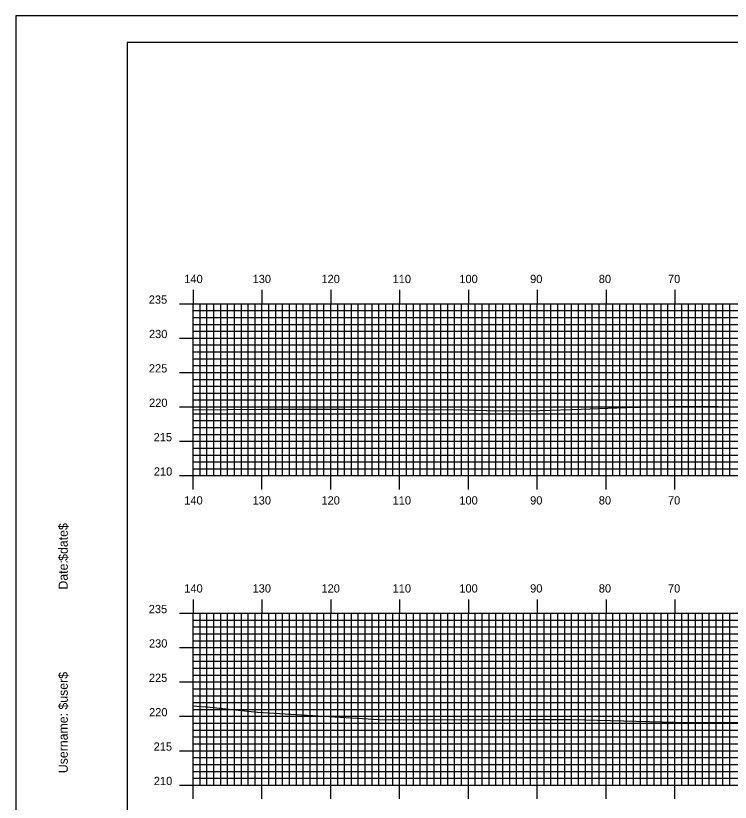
# Model space of a CAD drawing. Extents: x 1804290 to 1804634, y 442591 to 442811.
# Drawn here: x 1804290.4 to 1804394.2, y 442696.2 to 442810.5 of the extents above; entities that cross this region are included whole.
import ezdxf

# ---------------------------------------------------------------- set-up
doc = ezdxf.new("R2010")
doc.units = 0
for name, color, linetype in [('BORDER', 7, 'Continuous'), ('H_V ANNOTATION', 7, 'Continuous'), ('MAJOR', 7, 'Continuous'), ('MINOR', 7, 'Continuous'), ('PLOT BOUNDARY', 7, 'Continuous'), ('S_Roadway_Centerline', 7, 'Continuous')]:
    doc.layers.add(name, color=color, linetype=linetype)

msp = doc.modelspace()

# ---------------------------------------------------------------- linework, layer by layer
at = {"layer": 'BORDER'}
msp.add_lwpolyline([(1804306.57, 442596.67), (1804626.57, 442596.67), (1804626.57, 442806.67), (1804306.57, 442806.67)], close=True, dxfattribs=at)
at = {"layer": 'MAJOR'}
for p, q in [((1804316.17, 442770.67), (1804316.17, 442768.67)), ((1804326.17, 442770.67), (1804326.17, 442768.67)), ((1804336.17, 442770.67), (1804336.17, 442768.67)), ((1804346.17, 442770.67), (1804346.17, 442768.67)), ((1804356.17, 442770.67), (1804356.17, 442768.67)), ((1804366.17, 442770.67), (1804366.17, 442768.67)), ((1804376.17, 442770.67), (1804376.17, 442768.67)), ((1804386.17, 442770.67), (1804386.17, 442768.67)), ((1804314.16, 442768.67), (1804316.17, 442768.67)), ((1804316.17, 442768.67), (1804596.17, 442768.67)), ((1804316.17, 442743.67), (1804316.17, 442768.67)), ((1804316.17, 442743.67), (1804316.17, 442768.67)), ((1804316.17, 442768.67), (1804596.17, 442768.67)), ((1804326.17, 442743.67), (1804326.17, 442768.67)), ((1804336.17, 442743.67), (1804336.17, 442768.67)), ((1804346.17, 442743.67), (1804346.17, 442768.67)), ((1804356.17, 442743.67), (1804356.17, 442768.67)), ((1804366.17, 442743.67), (1804366.17, 442768.67)), ((1804376.17, 442743.67), (1804376.17, 442768.67)), ((1804386.17, 442743.67), (1804386.17, 442768.67)), ((1804314.16, 442763.67), (1804316.17, 442763.67)), ((1804316.17, 442763.67), (1804596.17, 442763.67)), ((1804314.16, 442758.67), (1804316.17, 442758.67)), ((1804316.17, 442758.67), (1804596.17, 442758.67)), ((1804314.16, 442753.67), (1804316.17, 442753.67)), ((1804316.17, 442753.67), (1804596.17, 442753.67)), ((1804314.16, 442748.67), (1804316.17, 442748.67)), ((1804316.17, 442748.67), (1804596.17, 442748.67)), ((1804314.16, 442743.67), (1804316.17, 442743.67)), ((1804316.17, 442743.67), (1804596.17, 442743.67)), ((1804316.17, 442743.67), (1804596.17, 442743.67)), ((1804316.17, 442741.66), (1804316.17, 442743.67)), ((1804326.17, 442741.66), (1804326.17, 442743.67)), ((1804336.17, 442741.66), (1804336.17, 442743.67)), ((1804346.17, 442741.66), (1804346.17, 442743.67)), ((1804356.17, 442741.66), (1804356.17, 442743.67)), ((1804366.17, 442741.66), (1804366.17, 442743.67)), ((1804376.17, 442741.66), (1804376.17, 442743.67)), ((1804386.17, 442741.66), (1804386.17, 442743.67)), ((1804316.17, 442725.67), (1804316.17, 442723.67)), ((1804326.17, 442725.67), (1804326.17, 442723.67)), ((1804336.17, 442725.67), (1804336.17, 442723.67)), ((1804346.17, 442725.67), (1804346.17, 442723.67)), ((1804356.17, 442725.67), (1804356.17, 442723.67)), ((1804366.17, 442725.67), (1804366.17, 442723.67)), ((1804376.17, 442725.67), (1804376.17, 442723.67)), ((1804386.17, 442725.67), (1804386.17, 442723.67)), ((1804314.16, 442723.67), (1804316.17, 442723.67)), ((1804316.17, 442723.67), (1804596.17, 442723.67)), ((1804316.17, 442698.67), (1804316.17, 442723.67)), ((1804316.17, 442698.67), (1804316.17, 442723.67)), ((1804316.17, 442723.67), (1804596.17, 442723.67)), ((1804326.17, 442698.67), (1804326.17, 442723.67)), ((1804336.17, 442698.67), (1804336.17, 442723.67)), ((1804346.17, 442698.67), (1804346.17, 442723.67)), ((1804356.17, 442698.67), (1804356.17, 442723.67)), ((1804366.17, 442698.67), (1804366.17, 442723.67)), ((1804376.17, 442698.67), (1804376.17, 442723.67)), ((1804386.17, 442698.67), (1804386.17, 442723.67)), ((1804314.16, 442718.67), (1804316.17, 442718.67)), ((1804316.17, 442718.67), (1804596.17, 442718.67)), ((1804314.16, 442713.67), (1804316.17, 442713.67)), ((1804316.17, 442713.67), (1804596.17, 442713.67)), ((1804314.16, 442708.67), (1804316.17, 442708.67)), ((1804316.17, 442708.67), (1804596.17, 442708.67)), ((1804314.16, 442703.67), (1804316.17, 442703.67)), ((1804316.17, 442703.67), (1804596.17, 442703.67)), ((1804314.16, 442698.67), (1804316.17, 442698.67)), ((1804316.17, 442698.67), (1804596.17, 442698.67)), ((1804316.17, 442698.67), (1804596.17, 442698.67)), ((1804316.17, 442696.66), (1804316.17, 442698.67)), ((1804326.17, 442696.66), (1804326.17, 442698.67)), ((1804336.17, 442696.66), (1804336.17, 442698.67)), ((1804346.17, 442696.66), (1804346.17, 442698.67)), ((1804356.17, 442696.66), (1804356.17, 442698.67)), ((1804366.17, 442696.66), (1804366.17, 442698.67)), ((1804376.17, 442696.66), (1804376.17, 442698.67)), ((1804386.17, 442696.66), (1804386.17, 442698.67))]:
    msp.add_line(p, q, dxfattribs=at)
at = {"layer": 'MINOR'}
for p, q in [((1804316.17, 442767.67), (1804596.17, 442767.67)), ((1804316.17, 442767.67), (1804318.17, 442767.67)), ((1804317.17, 442743.67), (1804317.17, 442768.67)), ((1804318.17, 442743.67), (1804318.17, 442768.67)), ((1804319.17, 442743.67), (1804319.17, 442768.67)), ((1804320.17, 442743.67), (1804320.17, 442768.67)), ((1804321.17, 442743.67), (1804321.17, 442768.67)), ((1804322.17, 442743.67), (1804322.17, 442768.67)), ((1804323.17, 442743.67), (1804323.17, 442768.67)), ((1804324.17, 442743.67), (1804324.17, 442768.67)), ((1804325.17, 442743.67), (1804325.17, 442768.67)), ((1804327.17, 442743.67), (1804327.17, 442768.67)), ((1804328.17, 442743.67), (1804328.17, 442768.67)), ((1804329.17, 442743.67), (1804329.17, 442768.67)), ((1804330.17, 442743.67), (1804330.17, 442768.67)), ((1804331.17, 442743.67), (1804331.17, 442768.67)), ((1804332.17, 442743.67), (1804332.17, 442768.67)), ((1804333.17, 442743.67), (1804333.17, 442768.67)), ((1804334.17, 442743.67), (1804334.17, 442768.67)), ((1804335.17, 442743.67), (1804335.17, 442768.67)), ((1804337.17, 442743.67), (1804337.17, 442768.67)), ((1804338.17, 442743.67), (1804338.17, 442768.67)), ((1804339.17, 442743.67), (1804339.17, 442768.67)), ((1804340.17, 442743.67), (1804340.17, 442768.67)), ((1804341.17, 442743.67), (1804341.17, 442768.67)), ((1804342.17, 442743.67), (1804342.17, 442768.67)), ((1804343.17, 442743.67), (1804343.17, 442768.67)), ((1804344.17, 442743.67), (1804344.17, 442768.67)), ((1804345.17, 442743.67), (1804345.17, 442768.67)), ((1804347.17, 442743.67), (1804347.17, 442768.67)), ((1804348.17, 442743.67), (1804348.17, 442768.67)), ((1804349.17, 442743.67), (1804349.17, 442768.67)), ((1804350.17, 442743.67), (1804350.17, 442768.67)), ((1804351.17, 442743.67), (1804351.17, 442768.67)), ((1804352.17, 442743.67), (1804352.17, 442768.67)), ((1804353.17, 442743.67), (1804353.17, 442768.67)), ((1804354.17, 442743.67), (1804354.17, 442768.67)), ((1804355.17, 442743.67), (1804355.17, 442768.67)), ((1804357.17, 442743.67), (1804357.17, 442768.67)), ((1804358.17, 442743.67), (1804358.17, 442768.67)), ((1804359.17, 442743.67), (1804359.17, 442768.67)), ((1804360.17, 442743.67), (1804360.17, 442768.67)), ((1804361.17, 442743.67), (1804361.17, 442768.67)), ((1804362.17, 442743.67), (1804362.17, 442768.67)), ((1804363.17, 442743.67), (1804363.17, 442768.67)), ((1804364.17, 442743.67), (1804364.17, 442768.67)), ((1804365.17, 442743.67), (1804365.17, 442768.67)), ((1804367.17, 442743.67), (1804367.17, 442768.67)), ((1804368.17, 442743.67), (1804368.17, 442768.67)), ((1804369.17, 442743.67), (1804369.17, 442768.67)), ((1804370.17, 442743.67), (1804370.17, 442768.67)), ((1804371.17, 442743.67), (1804371.17, 442768.67)), ((1804372.17, 442743.67), (1804372.17, 442768.67)), ((1804373.17, 442743.67), (1804373.17, 442768.67)), ((1804374.17, 442743.67), (1804374.17, 442768.67)), ((1804375.17, 442743.67), (1804375.17, 442768.67)), ((1804377.17, 442743.67), (1804377.17, 442768.67)), ((1804378.17, 442743.67), (1804378.17, 442768.67)), ((1804379.17, 442743.67), (1804379.17, 442768.67)), ((1804380.17, 442743.67), (1804380.17, 442768.67)), ((1804381.17, 442743.67), (1804381.17, 442768.67)), ((1804382.17, 442743.67), (1804382.17, 442768.67)), ((1804383.17, 442743.67), (1804383.17, 442768.67)), ((1804384.17, 442743.67), (1804384.17, 442768.67)), ((1804385.17, 442743.67), (1804385.17, 442768.67)), ((1804387.17, 442743.67), (1804387.17, 442768.67)), ((1804388.17, 442743.67), (1804388.17, 442768.67)), ((1804389.17, 442743.67), (1804389.17, 442768.67)), ((1804390.17, 442743.67), (1804390.17, 442768.67)), ((1804391.17, 442743.67), (1804391.17, 442768.67)), ((1804392.17, 442743.67), (1804392.17, 442768.67)), ((1804393.17, 442743.67), (1804393.17, 442768.67)), ((1804394.17, 442743.67), (1804394.17, 442768.67)), ((1804316.17, 442766.67), (1804596.17, 442766.67)), ((1804316.17, 442766.67), (1804318.17, 442766.67)), ((1804316.17, 442765.67), (1804596.17, 442765.67)), ((1804316.17, 442765.67), (1804318.17, 442765.67)), ((1804316.17, 442764.67), (1804596.17, 442764.67)), ((1804316.17, 442764.67), (1804318.17, 442764.67)), ((1804316.17, 442762.67), (1804596.17, 442762.67)), ((1804316.17, 442762.67), (1804318.17, 442762.67)), ((1804316.17, 442761.67), (1804596.17, 442761.67)), ((1804316.17, 442761.67), (1804318.17, 442761.67)), ((1804316.17, 442760.67), (1804596.17, 442760.67)), ((1804316.17, 442760.67), (1804318.17, 442760.67)), ((1804316.17, 442759.67), (1804596.17, 442759.67)), ((1804316.17, 442759.67), (1804318.17, 442759.67)), ((1804316.17, 442757.67), (1804596.17, 442757.67)), ((1804316.17, 442757.67), (1804318.17, 442757.67)), ((1804316.17, 442756.67), (1804596.17, 442756.67)), ((1804316.17, 442756.67), (1804318.17, 442756.67)), ((1804316.17, 442755.67), (1804596.17, 442755.67)), ((1804316.17, 442755.67), (1804318.17, 442755.67)), ((1804316.17, 442754.67), (1804596.17, 442754.67)), ((1804316.17, 442754.67), (1804318.17, 442754.67)), ((1804316.17, 442752.67), (1804596.17, 442752.67)), ((1804316.17, 442752.67), (1804318.17, 442752.67)), ((1804316.17, 442751.67), (1804596.17, 442751.67)), ((1804316.17, 442751.67), (1804318.17, 442751.67)), ((1804316.17, 442750.67), (1804596.17, 442750.67)), ((1804316.17, 442750.67), (1804318.17, 442750.67)), ((1804316.17, 442749.67), (1804596.17, 442749.67)), ((1804316.17, 442749.67), (1804318.17, 442749.67)), ((1804316.17, 442747.67), (1804596.17, 442747.67)), ((1804316.17, 442747.67), (1804318.17, 442747.67)), ((1804316.17, 442746.67), (1804596.17, 442746.67)), ((1804316.17, 442746.67), (1804318.17, 442746.67)), ((1804316.17, 442745.67), (1804596.17, 442745.67)), ((1804316.17, 442745.67), (1804318.17, 442745.67)), ((1804316.17, 442744.67), (1804596.17, 442744.67)), ((1804316.17, 442744.67), (1804318.17, 442744.67)), ((1804317.17, 442698.67), (1804317.17, 442723.67)), ((1804318.17, 442698.67), (1804318.17, 442723.67)), ((1804319.17, 442698.67), (1804319.17, 442723.67)), ((1804320.17, 442698.67), (1804320.17, 442723.67)), ((1804321.17, 442698.67), (1804321.17, 442723.67)), ((1804322.17, 442698.67), (1804322.17, 442723.67)), ((1804323.17, 442698.67), (1804323.17, 442723.67)), ((1804324.17, 442698.67), (1804324.17, 442723.67)), ((1804325.17, 442698.67), (1804325.17, 442723.67)), ((1804327.17, 442698.67), (1804327.17, 442723.67)), ((1804328.17, 442698.67), (1804328.17, 442723.67)), ((1804329.17, 442698.67), (1804329.17, 442723.67)), ((1804330.17, 442698.67), (1804330.17, 442723.67)), ((1804331.17, 442698.67), (1804331.17, 442723.67)), ((1804332.17, 442698.67), (1804332.17, 442723.67)), ((1804333.17, 442698.67), (1804333.17, 442723.67)), ((1804334.17, 442698.67), (1804334.17, 442723.67)), ((1804335.17, 442698.67), (1804335.17, 442723.67)), ((1804337.17, 442698.67), (1804337.17, 442723.67)), ((1804338.17, 442698.67), (1804338.17, 442723.67)), ((1804339.17, 442698.67), (1804339.17, 442723.67)), ((1804340.17, 442698.67), (1804340.17, 442723.67)), ((1804341.17, 442698.67), (1804341.17, 442723.67)), ((1804342.17, 442698.67), (1804342.17, 442723.67)), ((1804343.17, 442698.67), (1804343.17, 442723.67)), ((1804344.17, 442698.67), (1804344.17, 442723.67)), ((1804345.17, 442698.67), (1804345.17, 442723.67)), ((1804347.17, 442698.67), (1804347.17, 442723.67)), ((1804348.17, 442698.67), (1804348.17, 442723.67)), ((1804349.17, 442698.67), (1804349.17, 442723.67)), ((1804350.17, 442698.67), (1804350.17, 442723.67)), ((1804351.17, 442698.67), (1804351.17, 442723.67)), ((1804352.17, 442698.67), (1804352.17, 442723.67)), ((1804353.17, 442698.67), (1804353.17, 442723.67)), ((1804354.17, 442698.67), (1804354.17, 442723.67)), ((1804355.17, 442698.67), (1804355.17, 442723.67)), ((1804357.17, 442698.67), (1804357.17, 442723.67)), ((1804358.17, 442698.67), (1804358.17, 442723.67)), ((1804359.17, 442698.67), (1804359.17, 442723.67)), ((1804360.17, 442698.67), (1804360.17, 442723.67)), ((1804361.17, 442698.67), (1804361.17, 442723.67)), ((1804362.17, 442698.67), (1804362.17, 442723.67)), ((1804363.17, 442698.67), (1804363.17, 442723.67)), ((1804364.17, 442698.67), (1804364.17, 442723.67)), ((1804365.17, 442698.67), (1804365.17, 442723.67)), ((1804367.17, 442698.67), (1804367.17, 442723.67)), ((1804368.17, 442698.67), (1804368.17, 442723.67)), ((1804369.17, 442698.67), (1804369.17, 442723.67)), ((1804370.17, 442698.67), (1804370.17, 442723.67)), ((1804371.17, 442698.67), (1804371.17, 442723.67)), ((1804372.17, 442698.67), (1804372.17, 442723.67)), ((1804373.17, 442698.67), (1804373.17, 442723.67)), ((1804374.17, 442698.67), (1804374.17, 442723.67)), ((1804375.17, 442698.67), (1804375.17, 442723.67)), ((1804377.17, 442698.67), (1804377.17, 442723.67)), ((1804378.17, 442698.67), (1804378.17, 442723.67)), ((1804379.17, 442698.67), (1804379.17, 442723.67)), ((1804380.17, 442698.67), (1804380.17, 442723.67)), ((1804381.17, 442698.67), (1804381.17, 442723.67)), ((1804382.17, 442698.67), (1804382.17, 442723.67)), ((1804383.17, 442698.67), (1804383.17, 442723.67)), ((1804384.17, 442698.67), (1804384.17, 442723.67)), ((1804385.17, 442698.67), (1804385.17, 442723.67)), ((1804387.17, 442698.67), (1804387.17, 442723.67)), ((1804388.17, 442698.67), (1804388.17, 442723.67)), ((1804389.17, 442698.67), (1804389.17, 442723.67)), ((1804390.17, 442698.67), (1804390.17, 442723.67)), ((1804391.17, 442698.67), (1804391.17, 442723.67)), ((1804392.17, 442698.67), (1804392.17, 442723.67)), ((1804393.17, 442698.67), (1804393.17, 442723.67)), ((1804394.17, 442698.67), (1804394.17, 442723.67)), ((1804316.17, 442722.67), (1804596.17, 442722.67)), ((1804316.17, 442722.67), (1804318.17, 442722.67)), ((1804316.17, 442721.67), (1804596.17, 442721.67)), ((1804316.17, 442721.67), (1804318.17, 442721.67)), ((1804316.17, 442720.67), (1804596.17, 442720.67)), ((1804316.17, 442720.67), (1804318.17, 442720.67)), ((1804316.17, 442719.67), (1804596.17, 442719.67)), ((1804316.17, 442719.67), (1804318.17, 442719.67)), ((1804316.17, 442717.67), (1804596.17, 442717.67)), ((1804316.17, 442717.67), (1804318.17, 442717.67)), ((1804316.17, 442716.67), (1804596.17, 442716.67)), ((1804316.17, 442716.67), (1804318.17, 442716.67)), ((1804316.17, 442715.67), (1804596.17, 442715.67)), ((1804316.17, 442715.67), (1804318.17, 442715.67)), ((1804316.17, 442714.67), (1804596.17, 442714.67)), ((1804316.17, 442714.67), (1804318.17, 442714.67)), ((1804316.17, 442712.67), (1804596.17, 442712.67)), ((1804316.17, 442712.67), (1804318.17, 442712.67)), ((1804316.17, 442711.67), (1804596.17, 442711.67)), ((1804316.17, 442711.67), (1804318.17, 442711.67)), ((1804316.17, 442710.67), (1804596.17, 442710.67)), ((1804316.17, 442710.67), (1804318.17, 442710.67)), ((1804316.17, 442709.67), (1804596.17, 442709.67)), ((1804316.17, 442709.67), (1804318.17, 442709.67)), ((1804316.17, 442707.67), (1804596.17, 442707.67)), ((1804316.17, 442707.67), (1804318.17, 442707.67)), ((1804316.17, 442706.67), (1804596.17, 442706.67)), ((1804316.17, 442706.67), (1804318.17, 442706.67)), ((1804316.17, 442705.67), (1804596.17, 442705.67)), ((1804316.17, 442705.67), (1804318.17, 442705.67)), ((1804316.17, 442704.67), (1804596.17, 442704.67)), ((1804316.17, 442704.67), (1804318.17, 442704.67)), ((1804316.17, 442702.67), (1804596.17, 442702.67)), ((1804316.17, 442702.67), (1804318.17, 442702.67)), ((1804316.17, 442701.67), (1804596.17, 442701.67)), ((1804316.17, 442701.67), (1804318.17, 442701.67)), ((1804316.17, 442700.67), (1804596.17, 442700.67)), ((1804316.17, 442700.67), (1804318.17, 442700.67)), ((1804316.17, 442699.67), (1804596.17, 442699.67)), ((1804316.17, 442699.67), (1804318.17, 442699.67))]:
    msp.add_line(p, q, dxfattribs=at)
at = {"layer": 'PLOT BOUNDARY'}
msp.add_lwpolyline([(1804290.38, 442590.55), (1804630.38, 442590.55), (1804630.38, 442810.55), (1804290.38, 442810.55)], close=True, dxfattribs=at)
at = {"layer": 'S_Roadway_Centerline'}
for points in [[(1804316.17, 442753.25), (1804325.98, 442753.32), (1804338.25, 442753.35), (1804348.64, 442753.27), (1804355.57, 442753.23), (1804360.39, 442753.09), (1804366.49, 442753.14), (1804372.56, 442753.33), (1804379.03, 442753.56), (1804385.39, 442753.73), (1804390.07, 442753.77), (1804394.91, 442753.68)], [(1804316.17, 442710.21), (1804316.69, 442710.13), (1804318.63, 442709.99), (1804325.53, 442709.28), (1804343.18, 442708.23), (1804346.68, 442708.15), (1804364.53, 442708.2), (1804371.16, 442708.22), (1804388.1, 442707.77), (1804391.13, 442707.77), (1804393.95, 442707.75), (1804402.91, 442707.77)]]:
    msp.add_lwpolyline(points, dxfattribs=at)

# ---------------------------------------------------------------- texts
at = {"layer": 'BORDER'}
for s, p in [('$date$', (1804297.94, 442731.28)), ('Date:', (1804297.94, 442727.1)), ('$user$', (1804297.94, 442709.65)), ('Username:', (1804297.94, 442700.4))]:
    msp.add_text(s, height=1.339, rotation=90, dxfattribs=at).set_placement(p)
at = {"layer": 'H_V ANNOTATION'}
for s, p in [('140', (1804314.87, 442771.67)), ('130', (1804324.8, 442771.67)), ('120', (1804334.81, 442771.67)), ('110', (1804345.15, 442771.67)), ('100', (1804354.85, 442771.67)), ('90', (1804365.14, 442771.67)), ('80', (1804375.12, 442771.67)), ('70', (1804385.17, 442771.67)), ('235', (1804309.71, 442768.67)), ('230', (1804309.74, 442763.67)), ('225', (1804309.73, 442758.67)), ('220', (1804309.76, 442753.67)), ('215', (1804310.42, 442748.67)), ('210', (1804310.45, 442743.67)), ('140', (1804314.87, 442739.47)), ('130', (1804324.8, 442739.47)), ('120', (1804334.81, 442739.47)), ('110', (1804345.15, 442739.47)), ('100', (1804354.85, 442739.47)), ('90', (1804365.14, 442739.47)), ('80', (1804375.12, 442739.47)), ('70', (1804385.17, 442739.47)), ('140', (1804314.87, 442726.67)), ('130', (1804324.8, 442726.67)), ('120', (1804334.81, 442726.67)), ('110', (1804345.15, 442726.67)), ('100', (1804354.85, 442726.67)), ('90', (1804365.14, 442726.67)), ('80', (1804375.12, 442726.67)), ('70', (1804385.17, 442726.67)), ('235', (1804309.71, 442723.67)), ('230', (1804309.74, 442718.67)), ('225', (1804309.73, 442713.67)), ('220', (1804309.76, 442708.67)), ('215', (1804310.42, 442703.67)), ('210', (1804310.45, 442698.67))]:
    msp.add_text(s, height=1.2, dxfattribs=at).set_placement(p)
at = {"layer": 'MAJOR'}
for p in [(1804316.16, 442743.67), (1804316.16, 442698.67)]:
    msp.add_text('-', height=0.012, dxfattribs=at).set_placement(p)

doc.saveas('drawing.dxf')
